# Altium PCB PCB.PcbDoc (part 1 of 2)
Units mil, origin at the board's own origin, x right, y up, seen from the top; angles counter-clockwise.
Board outline 1610 x 1385 mil, 4 copper layers (Top Layer, Signal Layer 1, Signal Layer 2, Bottom Layer), stack 61.2 mil thick; 53 components, 26 nets, 134 pads, 40 vias.
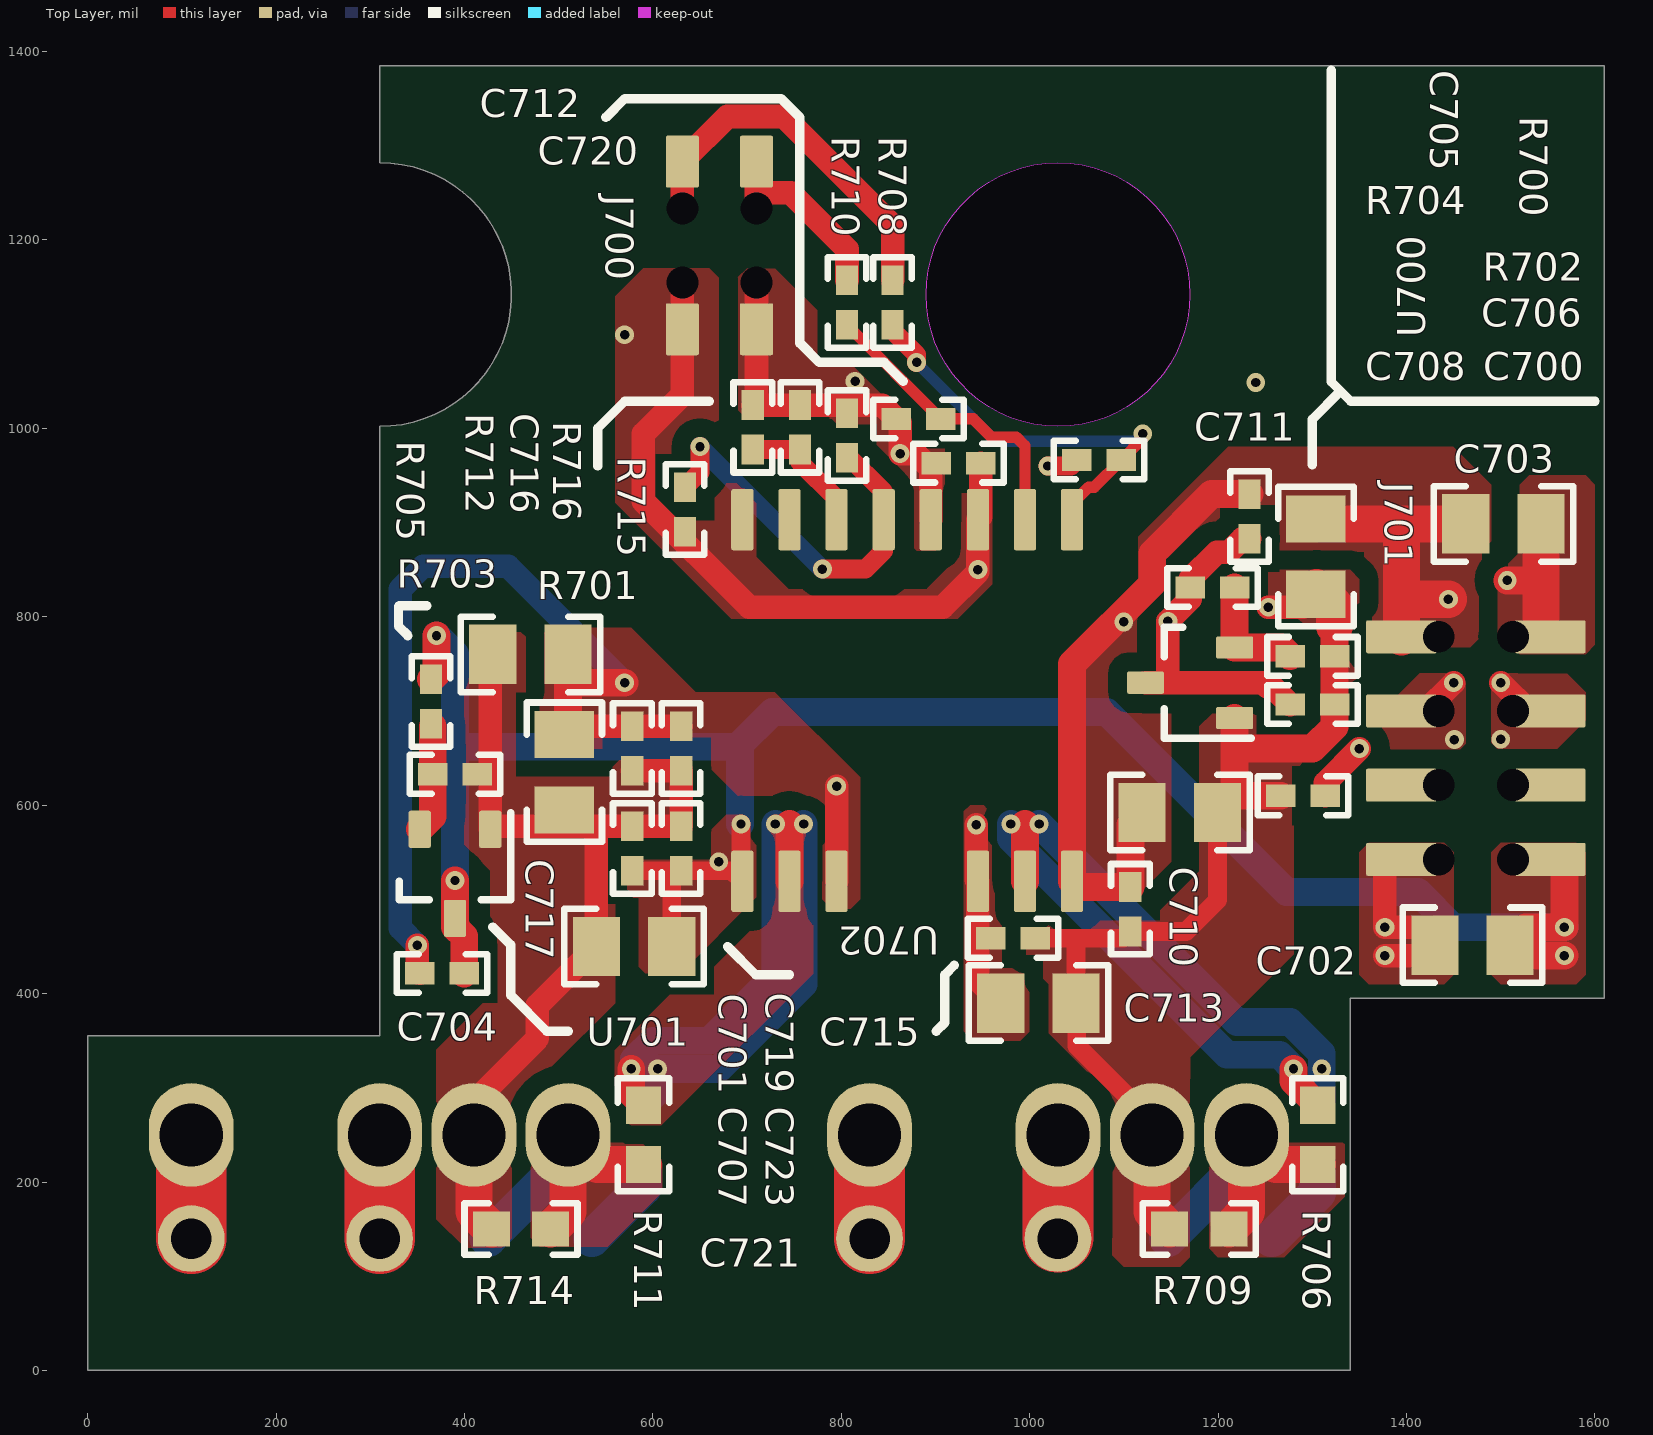
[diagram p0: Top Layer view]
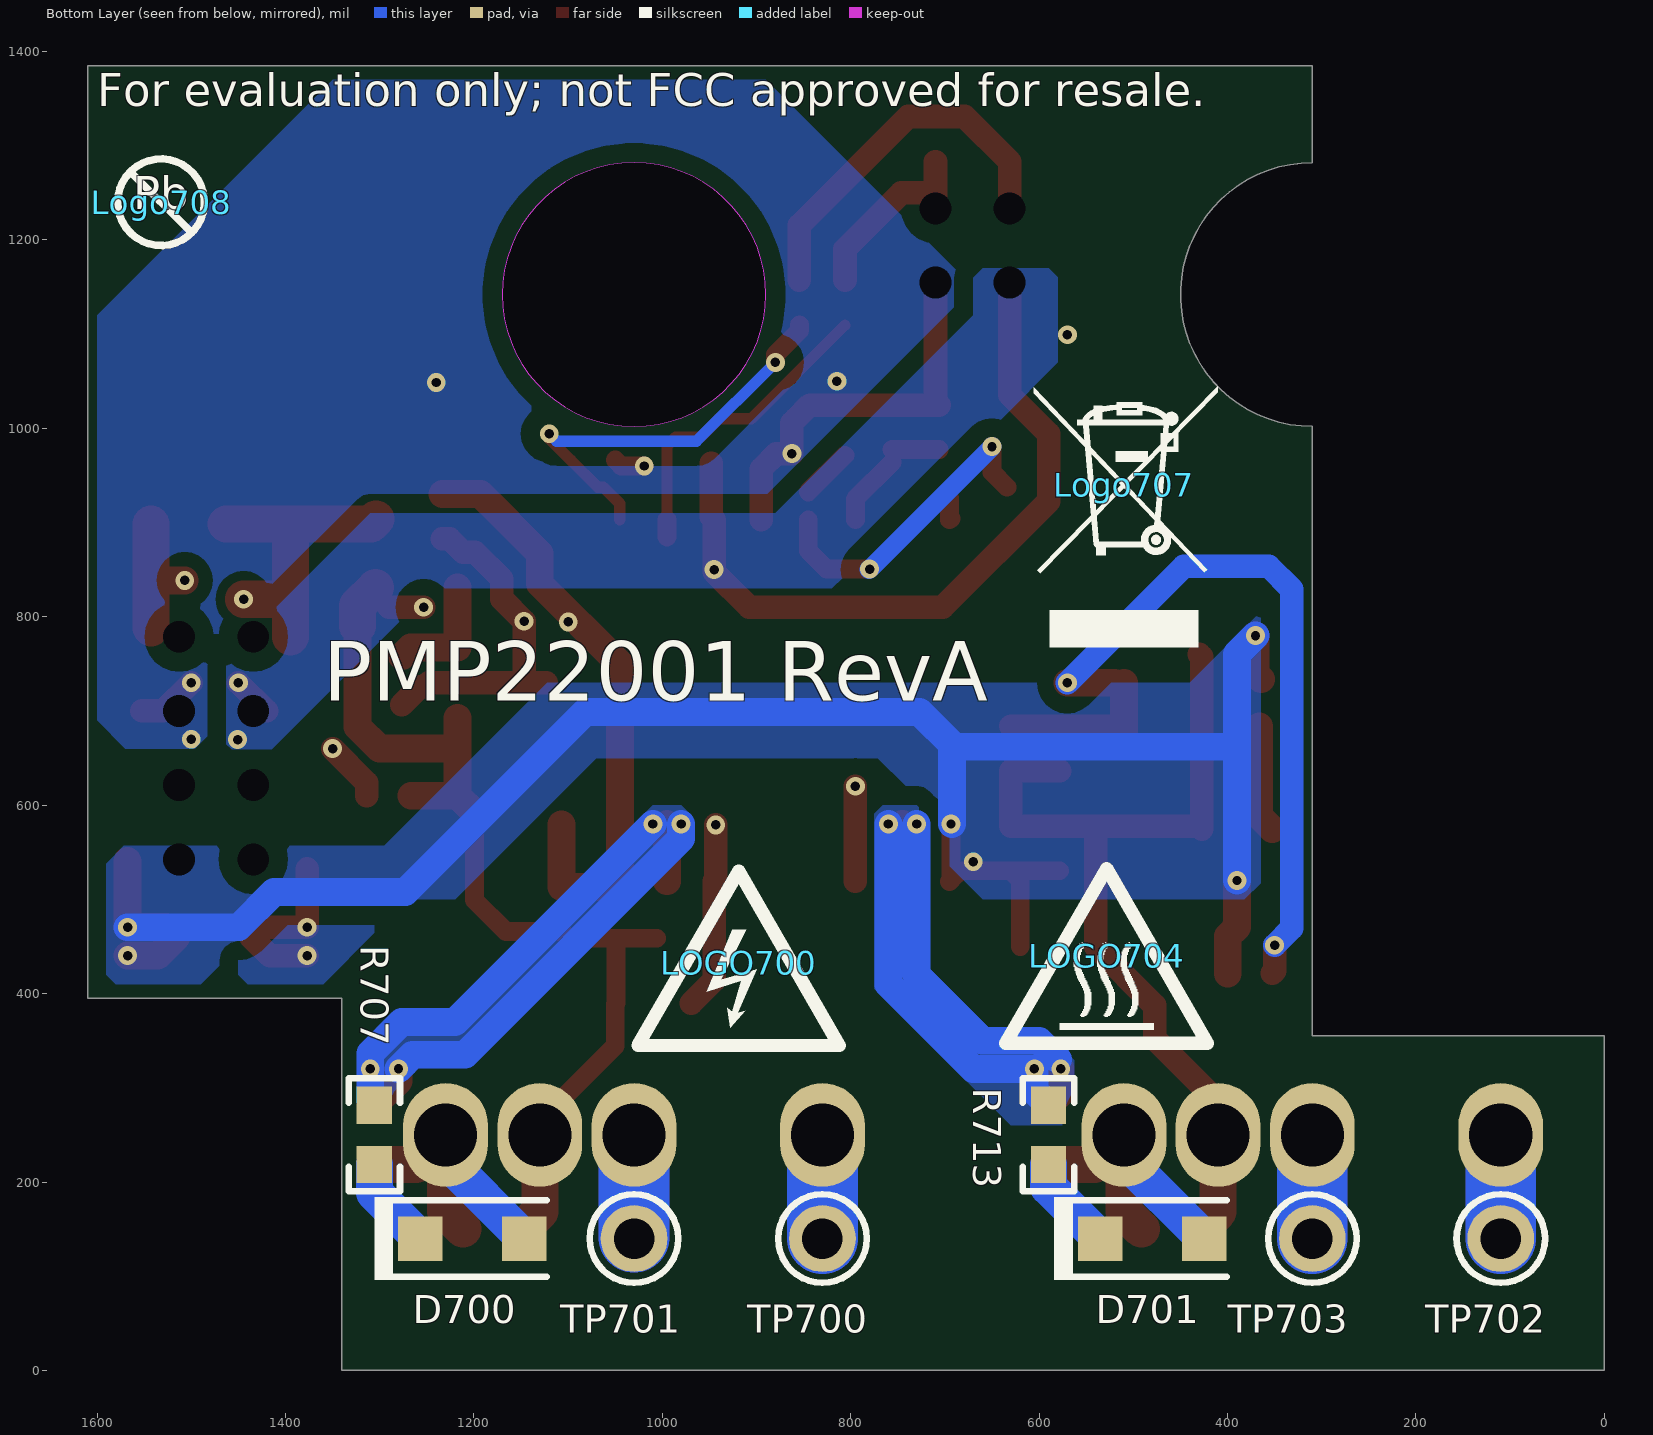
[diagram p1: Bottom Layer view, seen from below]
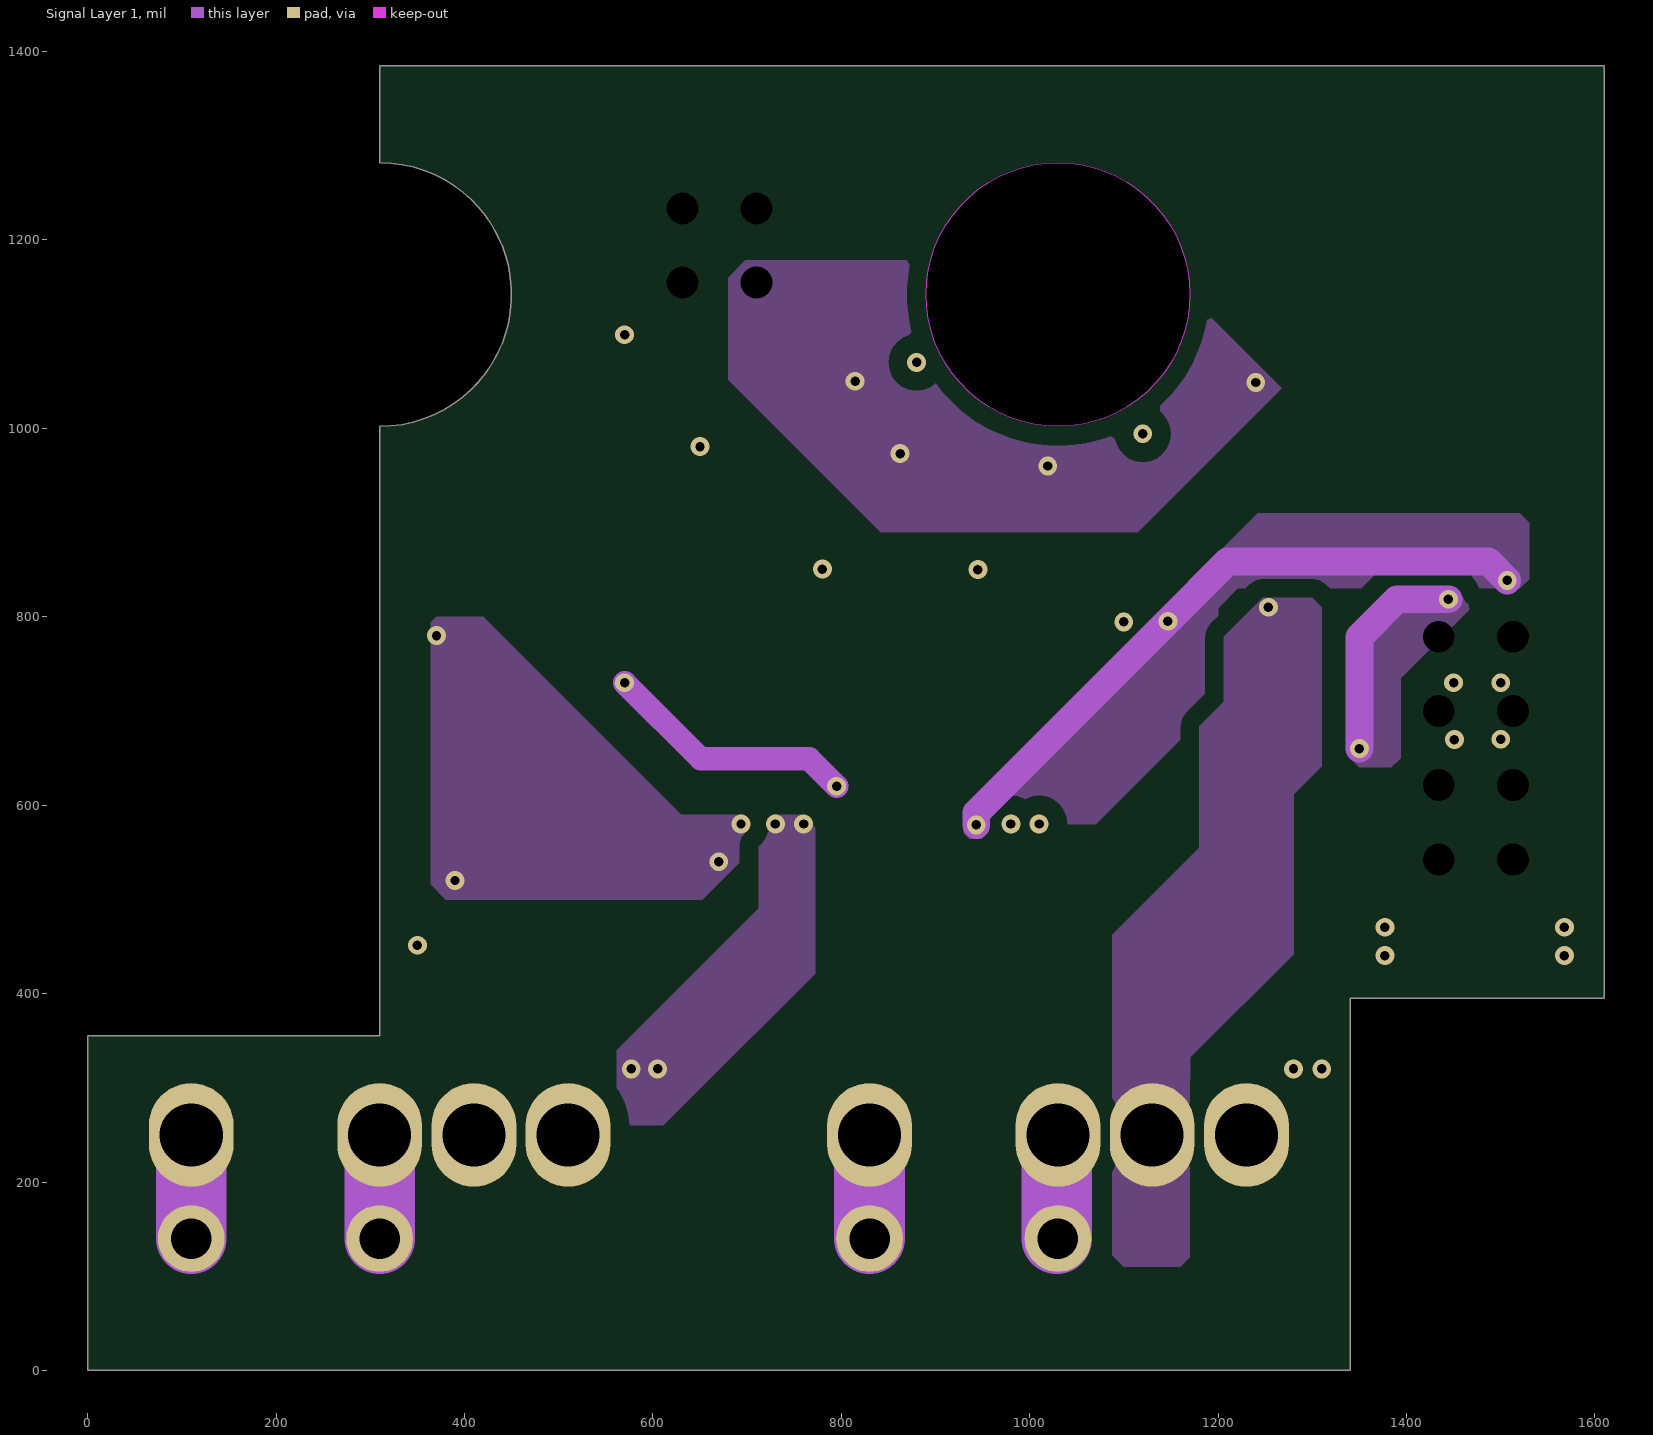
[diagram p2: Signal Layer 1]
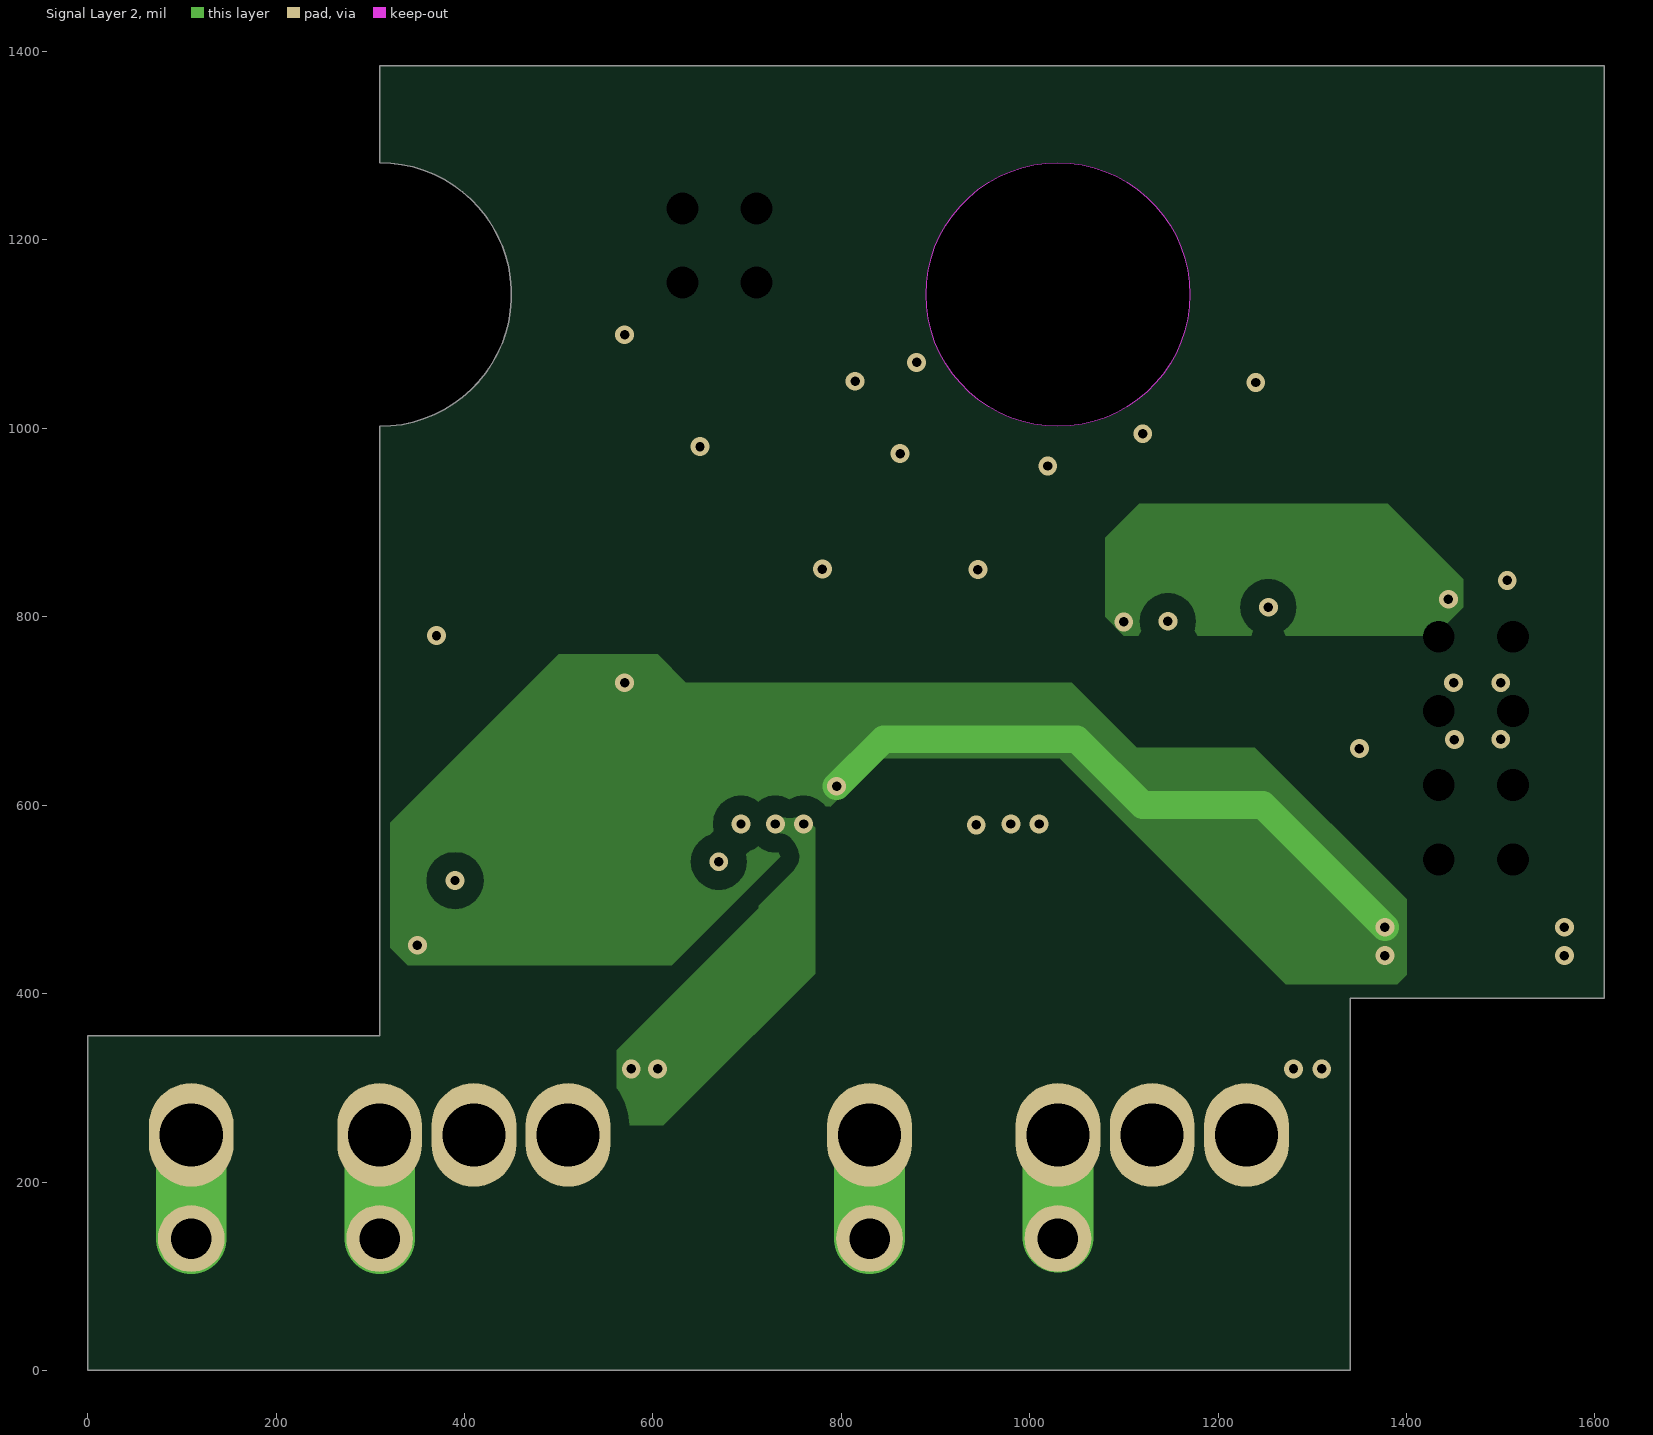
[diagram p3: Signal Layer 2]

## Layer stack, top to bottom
Top Solder: solder mask 0.4, Solder Resist, Dk 3.5
Top Layer: signal copper 1.4
Dielectric 3: dielectric 7.8, Dk 4.2
Signal Layer 1: signal copper 1.4
Dielectric 2: core 40, FR-4, Dk 4.2
Signal Layer 2: signal copper 1.4
Dielectric 4: dielectric 7.8, Dk 4.2
Bottom Layer: signal copper 1.4
Bottom Solder: solder mask 0.4, Solder Resist, Dk 3.5

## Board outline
0,0 0,355 310,355 310,1002 ccw(c310,1142) 310,1282 310,1385 1610,1385 1610,395 1340,395 1340,0
cut-out: 1030,1002 cw(c1030,1142) 890,1142 cw(c1030,1142) 1030,1282 cw(c1030,1142) 1170,1142 cw(c1030,1142)

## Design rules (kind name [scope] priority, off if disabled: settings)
AcuteAngle [All] p1: minimum=4.50000000000000E+0001 checktracksonly=FALSE
AssemblyTestPointUsage [All] p1: valid=2
Clearance Clearance_2 [InNetClass('HV') vs Not InNetClass('HV')] p1: gap=50 ignorepadtopadclearanceinfootprint=FALSE except(0: Arc-Hole Track-Hole SMDPad-Hole THPad-Hole Via-Hole Fill-Hole Poly-Hole Region-Hole Text-Hole)
Clearance Clearance_1 [InNetClass('MV') vs Not InNetClass('MV')] p2: gap=20 ignorepadtopadclearanceinfootprint=FALSE
Clearance Clearance_Keepouts [((IsTrack Or IsArc) And Not InPoly) And IsFree and IsKeepOut vs ((IsTrack Or IsArc) And Not InPoly) And IsFree and IsKeepOut] p3: gap=0 ignorepadtopadclearanceinfootprint=FALSE
Clearance Clearance_BoardEdge_MountingHoles [OnCopper and InComponentClass('Mounting Holes') vs IsKeepOut] p4: gap=40 ignorepadtopadclearanceinfootprint=FALSE except(0: Arc-Hole Track-Hole SMDPad-Hole THPad-Hole Via-Hole Fill-Hole Poly-Hole Region-Hole Text-Hole)
Clearance Clearance_BoardEdge_Poly [OnCopper and InPoly vs IsKeepOut] p5: gap=25 ignorepadtopadclearanceinfootprint=FALSE except(0: Arc-Hole Track-Hole SMDPad-Hole THPad-Hole Via-Hole Fill-Hole Poly-Hole Region-Hole Text-Hole)
Clearance Clearance_BoardEdge [OnCopper and Not InComponentClass('Logo') and not InComponentClass('FiducialMark') and not InRegion(1000,500,4000,800) and Not IsKeepout vs IsKeepOut] p6: gap=75 ignorepadtopadclearanceinfootprint=FALSE except(0: Arc-Hole Track-Hole SMDPad-Hole THPad-Hole Via-Hole Fill-Hole Poly-Hole Region-Hole Text-Hole)
Clearance Clearance_Poly [InPolygon] p7: gap=20 ignorepadtopadclearanceinfootprint=FALSE except(0: Arc-Hole Track-Hole SMDPad-Hole THPad-Hole Via-Hole Fill-Hole Poly-Hole Region-Hole Text-Hole)
Clearance [All] p8: gap=7.87 ignorepadtopadclearanceinfootprint=FALSE except(0: Arc-Hole Track-Hole SMDPad-Hole THPad-Hole Via-Hole Fill-Hole Poly-Hole Region-Hole Text-Hole)
ComponentClearance ComponentClearance_MountingHoles_FiducialMarks [InComponentClass('Mounting Holes') vs InComponentClass('FiducialMark')] p1: gap=20 collisioncheckmode=3 verticalgap=10 showdistances=FALSE
ComponentClearance ComponentClearance_Shunt [InComponentClass('Header') vs InComponentClass('Shunt')] p2: gap=0 collisioncheckmode=3 verticalgap=0 showdistances=FALSE
ComponentClearance ComponentClearance_Logo [InComponentClass('Logo')] p3: gap=5 collisioncheckmode=3 verticalgap=10 showdistances=FALSE
ComponentClearance ComponentClearance_ScrewToNut [(HasFootprint('NY PMS 440 0025 PH')) vs (HasFootprint('Keystone_1902C'))] p4: gap=20 collisioncheckmode=3 verticalgap=100000 showdistances=FALSE
ComponentClearance ComponentClearance_MountingHoles [InComponentClass('Mounting Holes')] p5: gap=20 collisioncheckmode=3 verticalgap=10 showdistances=FALSE
ComponentClearance ComponentClearance_SmallPassives [HasFootprint('0201*') or HasFootprint('0402*') or HasFootprint('0508') or HasFootprint('0603*') or HasFootprint('0612') or HasFootprint('0805*') or HasFootprint('0815*') or HasFootprint('0830*') or HasFootprint('1206*') or HasFootprint('1210*') or HasFootprint('1808*') or HasFootprint('1812*') or HasFootprint('1825*') or HasFootprint('2010*') or HasFootprint('2220*') or HasFootprint('2225*') or HasFootprint('2512*') or HasFootprint('2728*') or HasFootprint('3518*') vs HasFootprint('0201*') or HasFootprint('0402*') or HasFootprint('0508') or HasFootprint('0603*') or HasFootprint('0612') or HasFootprint('0805*') or HasFootprint('0815*') or HasFootprint('0830*') or HasFootprint('1206*') or HasFootprint('1210*') or HasFootprint('1808*') or HasFootprint('1812*') or HasFootprint('1825*') or HasFootprint('2010*') or HasFootprint('2220*') or HasFootprint('2225*') or HasFootprint('2512*') or HasFootprint('2728*') or HasFootprint('3518*')] p6: gap=20 collisioncheckmode=3 verticalgap=20 showdistances=FALSE
ComponentClearance ComponentClearance_THtoSMT [IsThruComponent vs IsSMTComponent] p7: gap=10 collisioncheckmode=3 verticalgap=10 showdistances=FALSE
ComponentClearance ComponentClearance_THtoTH [IsThruComponent vs IsThruComponent] p8: gap=10 collisioncheckmode=3 verticalgap=10 showdistances=FALSE
ComponentClearance [All] p9: gap=10 collisioncheckmode=3 verticalgap=10 showdistances=FALSE
DiffPairsRouting [All] p1: maxlimit=100 minlimit=10 mostfreqgap=10 toplayer_minwidth=15 toplayer_maxwidth=15 toplayer_prefwidth=15 midlayer1_minwidth=15 midlayer1_maxwidth=15 midlayer1_prefwidth=15 midlayer2_minwidth=15 midlayer2_maxwidth=15 midlayer2_prefwidth=15 bottomlayer_minwidth=15 bottomlayer_maxwidth=15 bottomlayer_prefwidth=15 maxuncoupledlength=1000
FabricationTestPointUsage TestPointUsage [All] p1: valid=2 allowmultiple=FALSE
FabricationTestpoint Testpoint [All] p1: side=3 testpointundercomponent=TRUE minsize=40 maxsize=100 preferedsize=60 minholesize=0 maxholesize=40 preferedholesize=32 testpointgrid=1 allowsidetop=TRUE allowsidebottom=TRUE usegrid=TRUE gridtolerance=0.01
FanoutControl Fanout_LCC [IsLCC] p1: bgadir=Out bgaviamode=Centered fanoutstyle=Auto fanoutdirection=Alternating viagrid=1 // Fanout_LCC (Default Rule)
FanoutControl Fanout_BGA [IsBGA] p2: bgadir=Out bgaviamode=Centered fanoutstyle=Auto fanoutdirection=Alternating viagrid=1 // Fanout_BGA (Default Rule)
FanoutControl Fanout_Default [All] p4: bgadir=Out bgaviamode=Centered fanoutstyle=Auto fanoutdirection=Alternating viagrid=1 // Fanout_Default (Default Rule)
FanoutControl Fanout_Small [(CompPinCount < 5)] p5: bgadir=Out bgaviamode=Centered fanoutstyle=Auto fanoutdirection=OutThenIn viagrid=1 // Fanout_Small (Default Rule)
Height [All] p1: minheight=0 maxheight=3000 prefheight=500
HoleSize [All] p1: absolutevalues=TRUE maxlimit=251 minlimit=7 maxpercent=80.000 minpercent=20.000
MinimumAnnularRing MinimumAnnularRing_ThermalPadVias [IsVia and InAnyComponent] p1: minimumring=5.91
MinimumAnnularRing [All] p2: minimumring=4.9
MinimumSolderMaskSliver MinimumSolderMaskSliver_Logo [InComponentClass('Logo') vs InComponentClass('Logo')] p1: minsoldermaskwidth=0.7
MinimumSolderMaskSliver [All] p2: minsoldermaskwidth=2
PlaneConnect [All] p1: planeconnectstyle=Direct reliefexpansion=10 reliefentries=4 reliefconductorwidth=10 reliefairgap=10
PolygonConnect PolygonConnect_21 [All vs IsNamedPolygon('VGB') Or  IsNamedPolygon('5VP') Or  IsNamedPolygon('+VB') Or  IsNamedPolygon('VGA') Or  IsNamedPolygon('+VB') Or  IsNamedPolygon('PGND') Or  IsNamedPolygon('COMA') Or  IsNamedPolygon('PGND') Or  IsNamedPolygon('-VB') Or  IsNamedPolygon('R711_1') Or  IsNamedPolygon('5Vp') Or  IsNamedPolygon('COMB') Or  IsNamedPolygon('5VP') Or  IsNamedPolygon('R706_1') Or  IsNamedPolygon('-VA') Or  IsNamedPolygon('-VB') Or  IsNamedPolygon('5VP') Or  IsNamedPolygon('PGND') Or  IsNamedPolygon('+VA')] p1: connectstyle=Direct reliefconductorwidth=10 reliefentries=4 polygonreliefangle="90 Angle" airgapwidth=10
PolygonConnect PolygonConnect_20 [All vs IsNamedPolygon('5Vp') Or  IsNamedPolygon('+VB') Or  IsNamedPolygon('-VB') Or  IsNamedPolygon('-VA') Or  IsNamedPolygon('COMA') Or  IsNamedPolygon('+VB') Or  IsNamedPolygon('-VB') Or  IsNamedPolygon('PGND') Or  IsNamedPolygon('+VA') Or  IsNamedPolygon('5VP') Or  IsNamedPolygon('PGND') Or  IsNamedPolygon('5VP') Or  IsNamedPolygon('PGND') Or  IsNamedPolygon('COMB') Or  IsNamedPolygon('VGB') Or  IsNamedPolygon('VGA') Or  IsNamedPolygon('5VP')] p2: connectstyle=Direct reliefconductorwidth=10 reliefentries=4 polygonreliefangle="90 Angle" airgapwidth=10
PolygonConnect PolygonConnect_19 [All vs IsNamedPolygon('+VB') Or  IsNamedPolygon('5Vp') Or  IsNamedPolygon('-VB') Or  IsNamedPolygon('-VB') Or  IsNamedPolygon('-VA') Or  IsNamedPolygon('COMA') Or  IsNamedPolygon('+VB')] p3: connectstyle=Direct reliefconductorwidth=10 reliefentries=4 polygonreliefangle="90 Angle" airgapwidth=10
PolygonConnect PolygonConnect_18 [All vs IsNamedPolygon('-VB') Or  IsNamedPolygon('+VB') Or  IsNamedPolygon('5Vp')] p4: connectstyle=Direct reliefconductorwidth=10 reliefentries=4 polygonreliefangle="90 Angle" airgapwidth=10
PolygonConnect PolygonConnect_17 [All vs IsNamedPolygon('4Vb') Or  IsNamedPolygon('4Va') Or  IsNamedPolygon('Comb') Or  IsNamedPolygon('PGND') Or  IsNamedPolygon('5Vp') Or  IsNamedPolygon('Comb') Or  IsNamedPolygon('Coma') Or  IsNamedPolygon('4Vb') Or  IsNamedPolygon('15Vb') Or  IsNamedPolygon('Coma') Or  IsNamedPolygon('15Va') Or  IsNamedPolygon('Comb') Or  IsNamedPolygon('Coma') Or  IsNamedPolygon('Comb') Or  IsNamedPolygon('4Vb') Or  IsNamedPolygon('15Vb') Or  IsNamedPolygon('15Va') Or  IsNamedPolygon('4Vb') Or  IsNamedPolygon('Coma') Or  IsNamedPolygon('4Va') Or  IsNamedPolygon('4Va') Or  IsNamedPolygon('4Va')] p5: connectstyle=Direct reliefconductorwidth=10 reliefentries=4 polygonreliefangle="90 Angle" airgapwidth=10
PolygonConnect PolygonConnect_16 [All vs IsNamedPolygon('15Va') Or  IsNamedPolygon('Coma') Or  IsNamedPolygon('4Vb') Or  IsNamedPolygon('Comb') Or  IsNamedPolygon('PGND') Or  IsNamedPolygon('15Vb') Or  IsNamedPolygon('4Va') Or  IsNamedPolygon('5Vp')] p6: connectstyle=Direct reliefconductorwidth=10 reliefentries=4 polygonreliefangle="90 Angle" airgapwidth=10
PolygonConnect PolygonConnect_15 [All vs IsNamedPolygon('C109_2') Or  IsNamedPolygon('C107_2') Or  IsNamedPolygon('HV') Or  IsNamedPolygon('Q203_5') Or  IsNamedPolygon('C107_2') Or  IsNamedPolygon('HS') Or  IsNamedPolygon('Q201_5') Or  IsNamedPolygon('Q203_5') Or  IsNamedPolygon('C106_2') Or  IsNamedPolygon('C108_2') Or  IsNamedPolygon('Vout') Or  IsNamedPolygon('Q203_5') Or  IsNamedPolygon('C108_2') Or  IsNamedPolygon('C113_2') Or  IsNamedPolygon('Q203_5') Or  IsNamedPolygon('Q201_5') Or  IsNamedPolygon('C107_2') Or  IsNamedPolygon('C102_1') Or  IsNamedPolygon('SGND') Or  IsNamedPolygon('GND') Or  IsNamedPolygon('SGND') Or  IsNamedPolygon('GND') Or  IsNamedPolygon('IN+') Or  IsNamedPolygon('IN+') Or  IsNamedPolygon('Q201_5') Or  IsNamedPolygon('Q201_5') Or  IsNamedPolygon('SGND') Or  IsNamedPolygon('SGND') Or  IsNamedPolygon('Vout') Or  IsNamedPolygon('Vout') Or  IsNamedPolygon('IN+') Or  IsNamedPolygon('GND') Or  IsNamedPolygon('IN+') Or  IsNamedPolygon('GND')] p7: connectstyle=Direct reliefconductorwidth=10 reliefentries=4 polygonreliefangle="90 Angle" airgapwidth=10
PolygonConnect PolygonConnect_14 [All vs IsNamedPolygon('C106_2') Or  IsNamedPolygon('C107_2') Or  IsNamedPolygon('C107_2') Or  IsNamedPolygon('C107_2') Or  IsNamedPolygon('C102_1') Or  IsNamedPolygon('Q203_5') Or  IsNamedPolygon('Vout') Or  IsNamedPolygon('Q203_5') Or  IsNamedPolygon('Q203_5') Or  IsNamedPolygon('Q201_5') Or  IsNamedPolygon('C108_2') Or  IsNamedPolygon('Q203_5') Or  IsNamedPolygon('HS') Or  IsNamedPolygon('HV') Or  IsNamedPolygon('C108_2') Or  IsNamedPolygon('Q201_5') Or  IsNamedPolygon('C109_2') Or  IsNamedPolygon('Q201_5') Or  IsNamedPolygon('Q201_5') Or  IsNamedPolygon('C113_2')] p8: connectstyle=Direct reliefconductorwidth=10 reliefentries=4 polygonreliefangle="90 Angle" airgapwidth=10
PolygonConnect PolygonConnect_13 [All vs IsNamedPolygon('C102_1') Or  IsNamedPolygon('HV') Or  IsNamedPolygon('C107_2') Or  IsNamedPolygon('C109_2') Or  IsNamedPolygon('C107_2') Or  IsNamedPolygon('C108_2') Or  IsNamedPolygon('C106_2') Or  IsNamedPolygon('C108_2') Or  IsNamedPolygon('C113_2') Or  IsNamedPolygon('C107_2')] p9: connectstyle=Direct reliefconductorwidth=10 reliefentries=4 polygonreliefangle="90 Angle" airgapwidth=10
PolygonConnect PolygonConnect_12 [All vs IsNamedPolygon('C107_2') Or  IsNamedPolygon('C113_2') Or  IsNamedPolygon('C106_2') Or  IsNamedPolygon('C107_2') Or  IsNamedPolygon('C107_2') Or  IsNamedPolygon('C102_1')] p10: connectstyle=Direct reliefconductorwidth=10 reliefentries=4 polygonreliefangle="90 Angle" airgapwidth=10
PolygonConnect PolygonConnect_11 [All vs IsNamedPolygon('C106_2') Or  IsNamedPolygon('C102_1') Or  IsNamedPolygon('C107_2') Or  IsNamedPolygon('C107_2') Or  IsNamedPolygon('C107_2')] p11: connectstyle=Direct reliefconductorwidth=10 reliefentries=4 polygonreliefangle="90 Angle" airgapwidth=10
PolygonConnect PolygonConnect_10 [All vs IsNamedPolygon('C106_2')] p12: connectstyle=Direct reliefconductorwidth=10 reliefentries=4 polygonreliefangle="90 Angle" airgapwidth=10
PolygonConnect PolygonConnect_9 [All vs IsNamedPolygon('C11_1') Or  IsNamedPolygon('Vin') Or  IsNamedPolygon('Vin') Or  IsNamedPolygon('5V') Or  IsNamedPolygon('D6_2') Or  IsNamedPolygon('Q3_3') Or  IsNamedPolygon('GND2') Or  IsNamedPolygon('GND2') Or  IsNamedPolygon('GND') Or  IsNamedPolygon('Q3_4') Or  IsNamedPolygon('12V5') Or  IsNamedPolygon('GND') Or  IsNamedPolygon('12V5') Or  IsNamedPolygon('D3_1')] p13: connectstyle=Direct reliefconductorwidth=10 reliefentries=4 polygonreliefangle="90 Angle" airgapwidth=10
PolygonConnect PolygonConnect_8 [All vs IsNamedPolygon('C11_1') Or  IsNamedPolygon('Vin') Or  IsNamedPolygon('12V5') Or  IsNamedPolygon('Q3_3') Or  IsNamedPolygon('GND2') Or  IsNamedPolygon('GND2') Or  IsNamedPolygon('5V') Or  IsNamedPolygon('Q3_4') Or  IsNamedPolygon('12V5')] p14: connectstyle=Direct reliefconductorwidth=10 reliefentries=4 polygonreliefangle="90 Angle" airgapwidth=10
PolygonConnect PolygonConnect_7 [All vs IsNamedPolygon('GND2') Or  IsNamedPolygon('GND2') Or  IsNamedPolygon('5V') Or  IsNamedPolygon('12V5') Or  IsNamedPolygon('12V5') Or  IsNamedPolygon('C11_1')] p15: connectstyle=Direct reliefconductorwidth=10 reliefentries=4 polygonreliefangle="90 Angle" airgapwidth=10
PolygonConnect PolygonConnect_6 [All vs IsNamedPolygon('GND2') Or  IsNamedPolygon('SGND') Or  IsNamedPolygon('GND1') Or  IsNamedPolygon('C901_1') Or  IsNamedPolygon('SGND') Or  IsNamedPolygon('GND2') Or  IsNamedPolygon('GND1')] p16: connectstyle=Direct reliefconductorwidth=10 reliefentries=4 polygonreliefangle="90 Angle" airgapwidth=10
PolygonConnect PolygonConnect_5 [All vs IsNamedPolygon('GND1') Or  IsNamedPolygon('GND1')] p17: connectstyle=Direct reliefconductorwidth=10 reliefentries=4 polygonreliefangle="90 Angle" airgapwidth=10
PolygonConnect PolygonConnect_4 [All vs IsNamedPolygon('C21_1') Or  IsNamedPolygon('C5_1') Or  IsNamedPolygon('C12_2') Or  IsNamedPolygon('C2_2') Or  IsNamedPolygon('C13_1') Or  IsNamedPolygon('C28_1') Or  IsNamedPolygon('C6_1') Or  IsNamedPolygon('GND') Or  IsNamedPolygon('GND2') Or  IsNamedPolygon('C14_1') Or  IsNamedPolygon('C13_1') Or  IsNamedPolygon('Q1_3') Or  IsNamedPolygon('C14_1') Or  IsNamedPolygon('C5_1') Or  IsNamedPolygon('GND2') Or  IsNamedPolygon('C28_1') Or  IsNamedPolygon('D5_2') Or  IsNamedPolygon('D6_2') Or  IsNamedPolygon('D2_1') Or  IsNamedPolygon('C12_2') Or  IsNamedPolygon('D2_1') Or  IsNamedPolygon('C4_1') Or  IsNamedPolygon('C4_1') Or  IsNamedPolygon('C2_2') Or  IsNamedPolygon('GND') Or  IsNamedPolygon('C33_1') Or  IsNamedPolygon('C9_1')] p18: connectstyle=Direct reliefconductorwidth=10 reliefentries=4 polygonreliefangle="90 Angle" airgapwidth=10
PolygonConnect PolygonConnect_3 [All vs IsNamedPolygon('C28_1') Or  IsNamedPolygon('C12_2') Or  IsNamedPolygon('C28_1') Or  IsNamedPolygon('C9_1') Or  IsNamedPolygon('D5_2') Or  IsNamedPolygon('C12_2') Or  IsNamedPolygon('C2_2') Or  IsNamedPolygon('C14_1') Or  IsNamedPolygon('C4_1') Or  IsNamedPolygon('C14_1') Or  IsNamedPolygon('D6_2') Or  IsNamedPolygon('GND2') Or  IsNamedPolygon('Q1_3') Or  IsNamedPolygon('C5_1') Or  IsNamedPolygon('D2_1') Or  IsNamedPolygon('C4_1') Or  IsNamedPolygon('C13_1') Or  IsNamedPolygon('C5_1') Or  IsNamedPolygon('C13_1') Or  IsNamedPolygon('C33_1') Or  IsNamedPolygon('D2_1') Or  IsNamedPolygon('GND') Or  IsNamedPolygon('GND') Or  IsNamedPolygon('GND2') Or  IsNamedPolygon('C2_2') Or  IsNamedPolygon('C6_1') Or  IsNamedPolygon('C21_1')] p19: connectstyle=Direct reliefconductorwidth=10 reliefentries=4 polygonreliefangle="90 Angle" airgapwidth=10
PolygonConnect PolygonConnect_2 [All vs IsNamedPolygon('C21_1') Or  IsNamedPolygon('C4_1') Or  IsNamedPolygon('D5_2') Or  IsNamedPolygon('C5_1') Or  IsNamedPolygon('C14_1') Or  IsNamedPolygon('C13_1') Or  IsNamedPolygon('C4_1') Or  IsNamedPolygon('C33_1') Or  IsNamedPolygon('C12_2') Or  IsNamedPolygon('D2_1') Or  IsNamedPolygon('C2_2') Or  IsNamedPolygon('C28_1') Or  IsNamedPolygon('C12_2') Or  IsNamedPolygon('D2_1') Or  IsNamedPolygon('C5_1') Or  IsNamedPolygon('Q1_3') Or  IsNamedPolygon('GND') Or  IsNamedPolygon('D6_2') Or  IsNamedPolygon('C6_1') Or  IsNamedPolygon('C2_2') Or  IsNamedPolygon('C14_1') Or  IsNamedPolygon('C28_1') Or  IsNamedPolygon('C13_1') Or  IsNamedPolygon('C9_1') Or  IsNamedPolygon('GND')] p20: connectstyle=Direct reliefconductorwidth=10 reliefentries=4 polygonreliefangle="90 Angle" airgapwidth=10
PolygonConnect PolygonConnect_1 [All vs IsNamedPolygon('C28_1') Or  IsNamedPolygon('D5_2') Or  IsNamedPolygon('C5_1') Or  IsNamedPolygon('C5_1') Or  IsNamedPolygon('D2_1') Or  IsNamedPolygon('C21_1') Or  IsNamedPolygon('C9_1') Or  IsNamedPolygon('C4_1') Or  IsNamedPolygon('C14_1') Or  IsNamedPolygon('C28_1') Or  IsNamedPolygon('C6_1') Or  IsNamedPolygon('C12_2') Or  IsNamedPolygon('C33_1') Or  IsNamedPolygon('C4_1') Or  IsNamedPolygon('C13_1') Or  IsNamedPolygon('C12_2') Or  IsNamedPolygon('D6_2') Or  IsNamedPolygon('C2_2') Or  IsNamedPolygon('C14_1') Or  IsNamedPolygon('D2_1') Or  IsNamedPolygon('C2_2') Or  IsNamedPolygon('C13_1')] p21: connectstyle=Direct reliefconductorwidth=10 reliefentries=4 polygonreliefangle="90 Angle" airgapwidth=10
PolygonConnect [All] p22: connectstyle=Relief reliefconductorwidth=10 reliefentries=4 polygonreliefangle="90 Angle" airgapwidth=10
RoutingVias ThermalPadVias [IsVia and InAnyComponent] p1: holewidth=7.87 width=19.68 viastyle="Through Hole" minholewidth=7.87 minwidth=19.68 maxholewidth=12.99 maxwidth=23.62
RoutingVias [All] p2: holewidth=16 width=34 viastyle="Through Hole" minholewidth=7.87 minwidth=20 maxholewidth=40 maxwidth=65
SilkToBoardRegionClearance [Not ((IsComment or IsDesignator) And (Hide <> 'False')) and not InRegion(1000,500,4000,800)] p1:
SilkToSilkClearance SilkToSilkClearance_Pb-FreeLogo [(HasFootprint('Pb-Free_Overlay_Medium') OR HasFootprint('Pb-Free_Overlay_Small')) vs (HasFootprint('Pb-Free_Overlay_Medium') OR HasFootprint('Pb-Free_Overlay_Small'))] p1: silktosilkclearance=0
SilkToSilkClearance [All] p2: silktosilkclearance=1
SilkToSolderMaskClearance "Silk to Solder Mask Opening" [All] p1: minsilkscreentomaskgap=1 clearancetoexposedcopper=FALSE
SolderMaskExpansion [All] p1: expansion=1.97
Width [All] p1: maxlimit=100 minlimit=6 preferedwidth=10 checkconnectedcopper=TRUE
14 further rules are at their usual default settings.

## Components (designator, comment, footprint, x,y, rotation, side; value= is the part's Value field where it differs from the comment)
C700 "C1005X7R1H104K050BB" 0402 1290,610 r180 top value=0.1uF
C701 "C1005X7R1H104K050BB" 0402 578.19,660 r270 top value=0.1uF
C702 "CGA4J3X5R1H475K125AB" 0805_HV 1470,451.35 r0 top value=4.7uF
C703 "CGA4J3X5R1H475K125AB" 0805_HV 1502.87,898.54 r0 top value=4.7uF
C704 "C1005X7R1H104K050BB" 0402 376.22,421.46 r0 top value=0.1uF
C705 "C1005X7R1H104K050BB" 0402 1233.34,906.5 r270 top value=0.1uF
C706 "C1005X7R1H104K050BB" 0402 1300,706.72 r180 top value=0.1uF
C707 "C1005X7R1H104K050BB" 0402 578.19,554 r270 top value=0.1uF
C708 "CGA4J3X5R1H475K125AB" 0805_HV 1159.34,592.14 r0 top value=4.7uF
C710 "GRM155R71H103KA88D" 0402 1106.82,489.59 r270 top value=0.01uF
C711 "0402YC101KAT2A" 0402 1073.62,966.35 r180 top value=100pF
C712 "0402YC101KAT2A" 0402 881.97,1010 r180 top value=100pF
C713 "CGA4J3X5R1H475K125AB" 0805_HV 1009.21,389.86 r180 top value=4.7uF
C715 "GRM155R71H103KA88D" 0402 982.29,458.72 r180 top value=0.01uF
C716 "885012205027" 0402 756.05,1001.07 r90 top value=2200pF
C717 "CGA4J3X5R1H475K125AB" 0805_HV 506,635 r270 top value=4.7uF
C719 "GRM155R71H103KA88D" 0402 630,660 r270 top value=0.01uF
C720 "0402YC104KAT2A" 0402 924.52,963 r180 top value=0.1uF
C721 "CGA4J3X5R1H475K125AB" 0805_HV 580,450 r0 top value=4.7uF
C723 "GRM155R71H103KA88D" 0402 630,554 r270 top value=0.01uF
D700 "SS14FL" SOD-123F 1201.65,140 r180 bottom value=40V
D701 "SS14FL" SOD-123F 480,140 r180 bottom value=40V
J700 "CLT-102-02-G-D-BE" Samtec_CLT-102-02-x-D-BE 670.63,1194.08 r0 top locked
J701 "CLT-104-02-G-D" FP-CLT-104-02-G-D_HDR8-MFG 1473.5,660.62 r90 top locked
LOGO700 "DANGER HIGH VOLTAGE" IEC_HighVoltage_Small 918.93,432.88 r180 bottom
LOGO704 "CAUTION HOT SURFACE" IEC_HotSurface_Small 528.37,440.38 r180 bottom
Logo707 "WEEE logo" WEEE_Minimum 510,940 r180 bottom
Logo708 "Pb-Free Symbol" Pb-Free_Overlay_Small 1532.04,1240 r180 bottom
Logo709 "FCC disclaimer" FCC_disclaimer 2160,820 r90 bottom
R700 "AC0805JR-074K7L" 0805_HV 1303.78,863.83 r90 top value=4.7k
R701 "AC0805JR-074K7L" 0805_HV 470,760 r0 top value=4.7k
R702 "CRCW04023K01FKED" 0402 1300,758 r0 top value=3.01k
R703 "CRCW04023K01FKED" 0402 390,632.8 r0 top value=3.01k
R704 "CRCW04024K99FKED" 0402 1193.91,830.93 r0 top value=4.99k
R705 "CRCW04024K99FKED" 0402 364.41,710 r270 top value=4.99k
R706 "CRCW06035R11FKEA" 0603 1305.66,250 r270 top value=5.11
R707 "RC0603FR-071RL" 0603 1305.66,250 r270 bottom value=1.00
R708 "CRCW04020000Z0ED" 0402 854.41,1133.62 r270 top value=0
R709 "CRCW060310K0FKEA" 0603 1180,150 r0 top value=10.0k
R710 "CRCW04020000Z0ED" 0402 806.05,1133.62 r270 top value=0
R711 "CRCW06035R11FKEA" 0603 590,250 r270 top value=5.11
R712 "CRCW04023K09FKED" 0402 706.05,1001.07 r270 top value=3.09k
R713 "RC0603FR-071RL" 0603 590,250 r270 bottom value=1.00
R714 "CRCW060310K0FKEA" 0603 460,150 r0 top value=10.0k
R715 "CRCW04025K10JNED" 0402 634.11,913.83 r270 top value=5.1k
R716 "CRCW04025K10JNED" 0402 806.05,992.26 r270 top value=5.1k
TP700 "3104-2-00-34-00-00-08-0" 3104-2 830,140 r90 bottom locked
TP701 "3104-2-00-34-00-00-08-0" 3104-2 1030,140 r90 bottom locked
TP702 "3104-2-00-34-00-00-08-0" 3104-2 110,140 r90 bottom locked
TP703 "3104-2-00-34-00-00-08-0" 3104-2 310,140 r90 bottom locked
U700 "TL431AQDBZRQ1" DBZ0003A_N 1170.29,730 r180 top
U701 "TL431AQDBZRQ1" DBZ0003A_N 390,527.14 r270 top
U702 "UCC21530QDWKRQ1" DWK0014A 870,711.07 r270 top

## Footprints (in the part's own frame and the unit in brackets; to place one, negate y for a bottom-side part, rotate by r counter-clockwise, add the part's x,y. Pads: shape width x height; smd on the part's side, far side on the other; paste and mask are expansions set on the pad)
0402 [mm] "0402 from SM-752 data"
  rect 0.8x0.6 smd: 1(-0.6,0) 2(0.6,0)
  silkscreen extent -1.22,-0.52 1.22,0.52, body extent -0.55,-0.3 0.55,0.3, height 0.6
0603 [mm] "0603 from SM-752 data"
  rect 1x0.95 smd: 1(-0.8,0) 2(0.8,0)
  silkscreen extent -1.52,-0.69 1.52,0.69, body extent -0.87,-0.47 0.87,0.47, height 1
0805_HV [mil] "0805 with 30mil clearance between pads"
  rect 50x63 smd: 1(-40,0) 2(40,0)
  silkscreen extent -74,-40 74,40, body extent -43,-29 43,29, height 57
3104-2 [mm] "Mill-Max Printed Circuit Pins"
  round 1.8 hole 1.092: 1(0,0)
  silkscreen extent -1.19,-1.19 1.19,1.19, body extent -0.88,-0.89 0.9,0.89, height 1.68
DBZ0003A_N [mm] "SOT23, 3-Leads, Body 2.9x1.3mm, Pitch 0.95mm, Lead Span 2.4mm, IPC Medium Density"
  rrect17% 1x0.6 smd: 1(-1.2,0.95) 2(-1.2,-0.95) 3(1.2,0)
  silkscreen extent -1.65,-1.5 0.7,1.5, body extent -1.26,-1.46 1.26,1.46, height 0.98
DWK0014A [mm] "SOIC-14"
  rrect17% 1.65x0.6 smd: 1(-4.875,4.445) 2(-4.875,3.175) 3(-4.875,1.905) 4(-4.875,0.635) 5(-4.875,-0.635) 6(-4.875,-1.905) 7(-4.875,-3.175) 8(-4.875,-4.445) 9(4.875,-4.445) 10(4.875,-3.175) 11(4.875,-1.905) 14(4.875,1.905) 15(4.875,3.175) 16(4.875,4.445)
  body extent -5.17,-5.15 5.17,5.15, height 2.59
FCC_disclaimer [mil]
FP-CLT-104-02-G-D_HDR8-MFG [mm]
  rrect11% 0.89x1.91 smd paste+0 mask+0: 1(3,-2.005) 2(3,2.005) 3(1,-2.005) 4(1,2.005) 5(-1,-2.005) 6(-1,2.005) 7(-3,-2.005) 8(-3,2.005)
  body extent -4.2,-3.06 4.2,3.06, height 0.25
IEC_HighVoltage_Small [mil]
  silkscreen extent -107,-88 107,97
IEC_HotSurface_Small [mil]
  silkscreen extent -107,-93 107,92
Pb-Free_Overlay_Small [mil]
  silkscreen extent -46,-46 46,46
Samtec_CLT-102-02-x-D-BE [mm] "Receptacle, 2mm, 2x2, SMT"
  rrect11% 0.89x1.4 smd: 1(-1,2.26) 2(-1,-2.26) 3(1,2.26) 4(1,-2.26)
  round 0.56 hole 0.86 unplated mask+0.102: ""(-1,-1) ""(-1,1) ""(1,1)
  round 0.56 hole 0.86 unplated mask+0.05: ""(1,-1)
  body extent -2,-2.58 2,2.58, height 2.29
SOD-123F [mm] "NXP recommended land pattern"
  rect 1.2x1.2 smd paste-0.05: 1(-1.4,0) 2(1.4,0)
  silkscreen extent -2.64,-1.12 2.01,1.12, body extent -1.8,-0.85 1.8,0.85, height 1.2
WEEE_Minimum [mil] "WEEElie bin"
  silkscreen extent -95,-172 99,104

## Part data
C700 C701 C704 C705 C706 C707: "CAP, CERM, 0.1 µF, 50 V,+/- 10%, X7R, 0402", Cap_Case=0402, Manufacturer=TDK, Supplier Part Number 1=445-5932-1-ND, TempCo=X7R, Tolerance_%=10, Value1="0.039064 ohm", Value2=50V, ValueDisplayed=0.1µF
C702 C703 C708 C713 C717 C721: library part GRT21BR61H475KE13L, "CAP, CERM, 4.7 µF, 50 V,+/- 10%, X5R, AEC-Q200 Grade 3, 0805", Cap_Case=0805, Manufacturer=TDK, TempCo=X5R, Tolerance_%=10, Value2=50V, ValueDisplayed=4.7µF
C710 C715 C719 C723: "CAP, CERM, 0.01 µF, 50 V,+/- 10%, X7R, 0402", Cap_Case=0402, Manufacturer=MuRata, Supplier Part Number 1=490-4516-1-ND, TempCo=X7R, Tolerance_%=10, Value2=50V, ValueDisplayed=0.01µF
C711 C712: "CAP, CERM, 100 pF, 16 V,+/- 10%, X7R, 0402", Cap_Case=0402, Manufacturer=AVX, Supplier Part Number 1=478-7887-1-ND, TempCo=X7R, Tolerance_%=10, Value2=16V, ValueDisplayed=100pF
C716: "CAP, CERM, 2200 pF, 16 V,+/- 10%, X7R, 0402", Cap_Case=0402, Manufacturer="Wurth Elektronik", TempCo=X7R, Tolerance_%=10, Value2=16V, ValueDisplayed=2200pF
C720: "CAP, CERM, 0.1 µF, 16 V,+/- 10%, X7R, 0402", Cap_Case=0402, Manufacturer=AVX, Supplier Part Number 1=478-7888-1-ND, TempCo=X7R, Tolerance_%=10, Value2=16V, ValueDisplayed=0.1µF
D700 D701: library part CMP-0028801-2, "Diode, Schottky, 40 V, 1 A, AEC-Q101, SOD-123F", Manufacturer="Fairchild Semiconductor", Value1=1A, Value2=0.55V
J700: library part CMP-0082275-1, "Receptacle, 2mm, 2x2, Gold, SMT", Color=Black, Current_A=4.1A, Manufacturer=Samtec, Supplier Part Number 1=SAM11007-ND
J701: library part CMP-0086478-1, "CONN RCPT 8POS 0.079 GOLD SMD", Current_A=4.1A, Manufacturer=Samtec
LOGO700: library part IEC_HighVoltage, "IEC 61010-1 High Voltage Warning"
LOGO704: library part IEC_HotSurface, "IEC 61010-1 Hot Surface Warning"
Logo707: library part CMP-0074769-1
Logo708: library part CMP-0074839-1
Logo709: library part CMP-0074847-1, "FCC_disclaimer"
R700 R701: library part CRCW08054K70JNEA, "RES, 4.7 k, 5%, 0.125 W, 0805", Manufacturer="Yageo America", Power_W=0.125, TempCo="200 ppm/C", Tolerance_%=5, Value1=5%, Value2=0.125W, Value_Code=4k70, ValueDisplayed=4.7k
R702 R703: "RES, 3.01 k, 1%, 0.063 W, 0402", Manufacturer=Vishay-Dale, Power_W=0.063, Supplier Part Number 1=541-3.01KLCT-ND, TempCo="100 ppm/C", Tolerance_%=1, Value1=1%, Value2=0.063W, Value_Code=3k01, ValueDisplayed=3.01k
R704 R705: "RES, 4.99 k, 1%, 0.063 W, 0402", Manufacturer=Vishay-Dale, Power_W=0.063, Supplier Part Number 1=541-4.99KLCT-ND, TempCo="100 ppm/C", Tolerance_%=1, Value1=1%, Value2=0.063W, Value_Code=4k99, ValueDisplayed=4.99k
R706 R711: "RES, 5.11, 1%, 0.1 W, 0603", Manufacturer=Vishay-Dale, Power_W=0.1, Supplier Part Number 1=541-5.11HHCT-ND, TempCo="100 ppm/C", Tolerance_%=1, Value1=1%, Value2=0.1W, Value_Code=5R11, ValueDisplayed=5.11
R707 R713: "RES, 1.00, 1%, 0.1 W, 0603", Manufacturer="Yageo America", Power_W=0.1, Supplier Part Number 1=311-1.00HRCT-ND, TempCo="200 ppm/C", Tolerance_%=1, Value1=1%, Value2=0.1W, Value_Code=1R00, ValueDisplayed=1.00
R708 R710: "RES, 0, 5%, 0.063 W, 0402", Manufacturer=Vishay-Dale, Power_W=0.063, Supplier Part Number 1=541-0.0JCT-ND, TempCo="200 ppm/C", Tolerance_%=5, Value1=5%, Value2=0.063W, Value_Code=0000, ValueDisplayed=0
R709 R714: "RES, 10.0 k, 1%, 0.1 W, 0603", Manufacturer=Vishay-Dale, Power_W=0.1, Supplier Part Number 1=541-10.0KHCT-ND, TempCo="100 ppm/C", Tolerance_%=1, Value1=1%, Value2=0.1W, Value_Code=10k0, ValueDisplayed=10.0k
R712: "RES, 3.09 k, 1%, 0.063 W, 0402", Manufacturer=Vishay-Dale, Power_W=0.063, Supplier Part Number 1=541-3.09KLCT-ND, TempCo="100 ppm/C", Tolerance_%=1, Value1=1%, Value2=0.063W, Value_Code=3k09, ValueDisplayed=3.09k
R715 R716: "RES, 5.1 k, 5%, 0.063 W, 0402", Manufacturer=Vishay-Dale, Power_W=0.063, Supplier Part Number 1=541-5.1KJCT-ND, TempCo="200 ppm/C", Tolerance_%=5, Value1=5%, Value2=0.063W, Value_Code=5k10, ValueDisplayed=5.1k
TP700 TP701 TP702 TP703: library part CMP-0055001-1, "PCB Pin, Swage Mount, TH", Manufacturer=Mill-Max, Supplier Part Number 1=3104-200340000080-ND
U700 U701: "Automotive Catalog Adjustable Precision Shunt Regulator, 34 ppm / degC, 100 mA, -40 to 125 degC, 3-pin SOT-23 (DBZ), Green (RoHS & no Sb/Br)", Alternate Manufacturer="Texas Instruments", Alternate PartNumber=Equivalent, Rating=Automotive, Supplier Part Number 1=296-21853-2-ND, Temp Coeff(Typ)(ppm/ degree C)=34
U702: library part CMP-0083997-1, "4-A, 6-A, 5.7-kVRMS Isolated Dual-Channel Gate Driver with Enable, DWK0014A (SOIC-14)", Alternate Manufacturer="Texas Instruments", Alternate PartNumber=UCC21530QDWKQ1

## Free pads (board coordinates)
  oval 90x110 hole 67: 1(110,250) 1(310,250) 1(410,250) 1(510,250) 1(830,250) 1(1030,250) 1(1130,250) 1(1230,250)
  round 22.05 hole 33.86 unplated mask+4: 1(1434.13,542.51) 1(1434.13,621.25) 1(1434.13,699.99) 1(1434.13,778.73) 1(1512.87,542.51) 1(1512.87,621.25) 1(1512.87,699.99) 1(1512.87,778.73)

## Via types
v1: diameter 20, hole 10, Top Layer to Bottom Layer, 40 vias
